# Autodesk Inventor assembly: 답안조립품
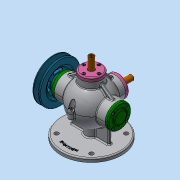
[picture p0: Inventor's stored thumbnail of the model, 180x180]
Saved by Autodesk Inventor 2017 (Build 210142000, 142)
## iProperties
Part Number: 답안조립품
Material: 일반
Document SubType Name: Assembly
Designer: MRC
Mass: 3733.58 g
Surface Area: 2584.17 cm^2
Volume: 938.795 cm^3
Density: 3.97699 g/cm^3
Author: MRC
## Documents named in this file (17)
- C:\Users\MRC\Desktop\620909V1002\답안조립품.iam
- C:\Users\MRC\Desktop\620909V1002\본체.ipt
- C:\Users\MRC\Desktop\620909V1002\V-벨트풀리.ipt
- C:\Users\MRC\Desktop\620909V1002\너트-M8x1.ipt
- C:\Users\MRC\Desktop\620909V1002\뒤커버.ipt
- C:\Users\MRC\Desktop\620909V1002\베어링- 6202.ipt
- C:\Users\MRC\Desktop\620909V1002\본체커버.ipt
- C:\Users\MRC\Desktop\620909V1002\볼트 M4x0.7.ipt
- C:\Users\MRC\Desktop\620909V1002\슬라이드 커버.ipt
- C:\Users\MRC\Desktop\620909V1002\슬라이드.ipt
- C:\Users\MRC\Desktop\620909V1002\앞커버.ipt
- C:\Users\MRC\Desktop\620909V1002\오일실.ipt
- C:\Users\MRC\Desktop\620909V1002\와셔 8x17.ipt
- C:\Users\MRC\Desktop\620909V1002\축.ipt
- C:\Users\MRC\Desktop\620909V1002\키-4x4.ipt
- C:\Users\MRC\Desktop\620909V1002\가변스프링1.ipt
- C:\Users\MRC\Desktop\620909V1002\가변스프링2.ipt
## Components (20 placed, 4 different names)
1. V-벨트풀리:1
2. M4x0.7x12:9
3. 가변스프링1:1
4. 가변스프링2:1
5. M4x0.7x12:1
6. M4x0.7x12:3
7. M4x0.7x12:4
8. M4x0.7x12:5
9. M4x0.7x12:2
10. M4x0.7x12:6
11. M4x0.7x12:7
12. M4x0.7x12:8
13. M4x0.7x12:10
14. M4x0.7x12:12
15. M4x0.7x12:13
16. M4x0.7x12:14
17. M4x0.7x12:11
18. M4x0.7x12:15
19. M4x0.7x12:16
20. M4x0.7x12:17
